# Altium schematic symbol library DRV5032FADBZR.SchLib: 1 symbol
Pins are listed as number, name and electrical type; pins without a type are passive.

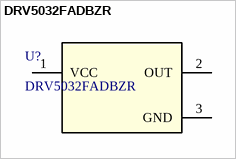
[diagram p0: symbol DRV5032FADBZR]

## DRV5032FADBZR
designator U?
Low-power (5Hz, <1ÂµA) low-voltage (up to 5.5V) switch 3-SOT-23 -40 to 85; Manufacturer_Name: Texas Instruments
footprint DBZ0003A-IPC_A
pins: 1 VCC (power), 2 OUT (oc), 3 GND (power)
